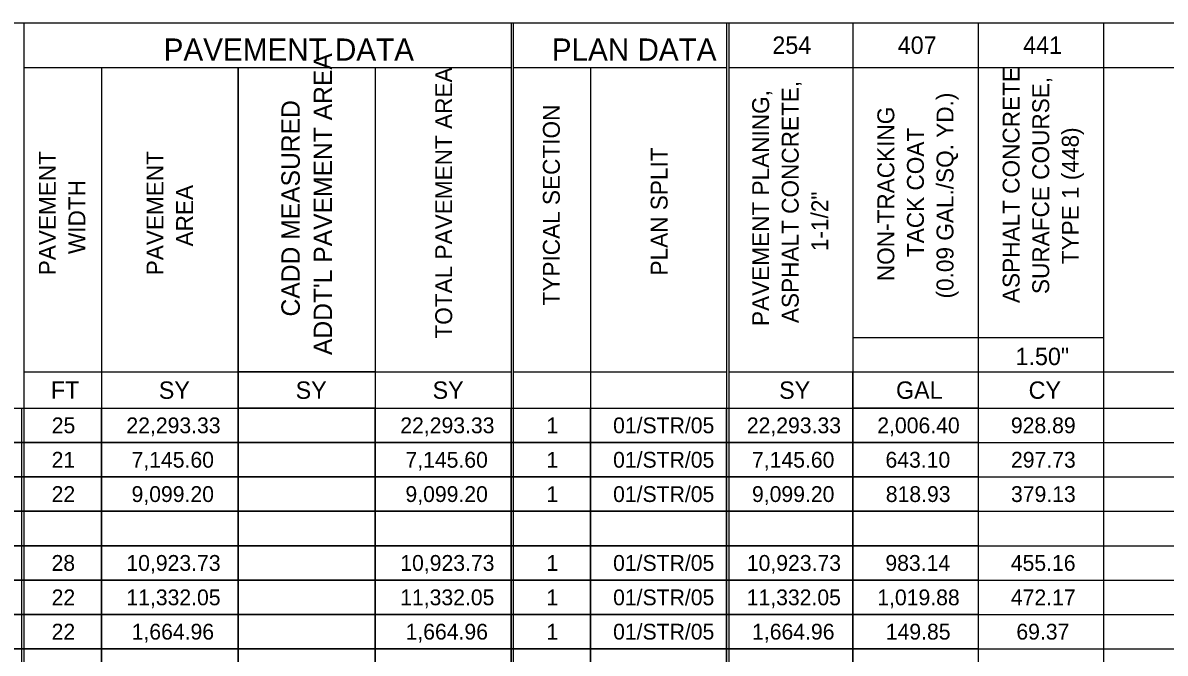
# Model space of a CAD drawing. Extents: x 0 to 34, y 0 to 22.
# Drawn here: x 9.08 to 20.36, y 6.59 to 12.82 of the extents above; entities that cross this region are included whole.
import ezdxf

# ---------------------------------------------------------------- set-up
doc = ezdxf.new("R2010")
doc.units = 0
doc.layers.add('Default', color=7, linetype='Continuous')

msp = doc.modelspace()

# ---------------------------------------------------------------- linework, layer by layer
at = {"layer": 'Default'}
for p, q in [((1.5, 12.819), (9.095, 12.819)), ((9.073, 12.819), (13.925, 12.819)), ((9.095, 12.819), (9.095, 1.862)), ((13.903, 12.819), (16.052, 12.819)), ((13.903, 12.819), (13.903, 1.183)), ((13.925, 12.819), (13.925, 1.183)), ((16.03, 12.819), (32, 12.819)), ((16.03, 12.819), (16.03, 0.503)), ((16.052, 12.819), (16.052, 0.503)), ((17.278, 12.819), (17.278, 0.503)), ((18.514, 12.819), (18.514, 0.503)), ((19.751, 12.819), (19.751, 0.503)), ((9.095, 12.378), (13.903, 12.378)), ((9.859, 12.378), (9.859, 1.862)), ((11.211, 12.378), (11.211, 1.862)), ((12.562, 12.378), (12.562, 1.862)), ((13.925, 12.378), (16.03, 12.378)), ((14.689, 12.378), (14.689, 1.862)), ((16.052, 12.378), (32, 12.378)), ((17.278, 9.711), (19.751, 9.711)), ((9.095, 9.371), (13.903, 9.371)), ((13.925, 9.371), (16.03, 9.371)), ((16.052, 9.371), (25.933, 9.371)), ((9.095, 9.014), (13.903, 9.014)), ((13.925, 9.014), (16.03, 9.014)), ((16.052, 9.014), (32, 9.014)), ((9.095, 8.674), (13.903, 8.674)), ((13.925, 8.674), (16.03, 8.674)), ((16.052, 8.674), (32, 8.674)), ((9.095, 8.335), (13.903, 8.335)), ((13.925, 8.335), (16.03, 8.335)), ((16.052, 8.335), (32, 8.335)), ((9.095, 7.995), (13.903, 7.995)), ((13.925, 7.995), (16.03, 7.995)), ((16.052, 7.995), (32, 7.995)), ((9.095, 7.655), (13.903, 7.655)), ((13.925, 7.655), (16.03, 7.655)), ((16.052, 7.655), (32, 7.655)), ((9.095, 7.315), (13.903, 7.315)), ((13.925, 7.315), (16.03, 7.315)), ((16.052, 7.315), (32, 7.315)), ((9.095, 6.976), (13.903, 6.976)), ((13.925, 6.976), (16.03, 6.976)), ((16.052, 6.976), (32, 6.976)), ((9.095, 6.636), (13.903, 6.636)), ((13.925, 6.636), (16.03, 6.636)), ((16.052, 6.636), (32, 6.636))]:
    msp.add_line(p, q, dxfattribs=at)
for points in [[(11.211, 12.378), (12.562, 12.378), (12.562, 9.371), (11.211, 9.371)], [(11.211, 9.371), (12.562, 9.371), (12.562, 9.014), (11.211, 9.014)], [(17.278, 9.371), (18.514, 9.371), (18.514, 9.014), (17.278, 9.014)], [(7.847, 9.014), (9.095, 9.014), (9.095, 8.674), (7.847, 8.674)], [(9.073, 9.014), (9.859, 9.014), (9.859, 8.674), (9.073, 8.674)], [(9.859, 9.014), (11.211, 9.014), (11.211, 8.674), (9.859, 8.674)], [(11.211, 9.014), (12.562, 9.014), (12.562, 8.674), (11.211, 8.674)], [(12.562, 9.014), (13.925, 9.014), (13.925, 8.674), (12.562, 8.674)], [(13.903, 9.014), (14.689, 9.014), (14.689, 8.674), (13.903, 8.674)], [(14.689, 9.014), (16.052, 9.014), (16.052, 8.674), (14.689, 8.674)], [(16.03, 9.014), (17.278, 9.014), (17.278, 8.674), (16.03, 8.674)], [(17.278, 9.014), (18.514, 9.014), (18.514, 8.674), (17.278, 8.674)], [(7.847, 8.674), (9.095, 8.674), (9.095, 8.335), (7.847, 8.335)], [(9.073, 8.674), (9.859, 8.674), (9.859, 8.335), (9.073, 8.335)], [(9.859, 8.674), (11.211, 8.674), (11.211, 8.335), (9.859, 8.335)], [(11.211, 8.674), (12.562, 8.674), (12.562, 8.335), (11.211, 8.335)], [(12.562, 8.674), (13.925, 8.674), (13.925, 8.335), (12.562, 8.335)], [(13.903, 8.674), (14.689, 8.674), (14.689, 8.335), (13.903, 8.335)], [(14.689, 8.674), (16.052, 8.674), (16.052, 8.335), (14.689, 8.335)], [(16.03, 8.674), (17.278, 8.674), (17.278, 8.335), (16.03, 8.335)], [(17.278, 8.674), (18.514, 8.674), (18.514, 8.335), (17.278, 8.335)], [(7.847, 8.335), (9.095, 8.335), (9.095, 7.995), (7.847, 7.995)], [(9.073, 8.335), (9.859, 8.335), (9.859, 7.995), (9.073, 7.995)], [(9.859, 8.335), (11.211, 8.335), (11.211, 7.995), (9.859, 7.995)], [(11.211, 8.335), (12.562, 8.335), (12.562, 7.995), (11.211, 7.995)], [(12.562, 8.335), (13.925, 8.335), (13.925, 7.995), (12.562, 7.995)], [(13.903, 8.335), (14.689, 8.335), (14.689, 7.995), (13.903, 7.995)], [(14.689, 8.335), (16.052, 8.335), (16.052, 7.995), (14.689, 7.995)], [(16.03, 8.335), (17.278, 8.335), (17.278, 7.995), (16.03, 7.995)], [(17.278, 8.335), (18.514, 8.335), (18.514, 7.995), (17.278, 7.995)], [(7.847, 7.995), (9.095, 7.995), (9.095, 7.655), (7.847, 7.655)], [(9.073, 7.995), (9.859, 7.995), (9.859, 7.655), (9.073, 7.655)], [(9.859, 7.995), (11.211, 7.995), (11.211, 7.655), (9.859, 7.655)], [(11.211, 7.995), (12.562, 7.995), (12.562, 7.655), (11.211, 7.655)], [(12.562, 7.995), (13.925, 7.995), (13.925, 7.655), (12.562, 7.655)], [(13.903, 7.995), (14.689, 7.995), (14.689, 7.655), (13.903, 7.655)], [(14.689, 7.995), (16.052, 7.995), (16.052, 7.655), (14.689, 7.655)], [(16.03, 7.995), (17.278, 7.995), (17.278, 7.655), (16.03, 7.655)], [(17.278, 7.995), (18.514, 7.995), (18.514, 7.655), (17.278, 7.655)], [(7.847, 7.655), (9.095, 7.655), (9.095, 7.315), (7.847, 7.315)], [(9.073, 7.655), (9.859, 7.655), (9.859, 7.315), (9.073, 7.315)], [(9.859, 7.655), (11.211, 7.655), (11.211, 7.315), (9.859, 7.315)], [(11.211, 7.655), (12.562, 7.655), (12.562, 7.315), (11.211, 7.315)], [(12.562, 7.655), (13.925, 7.655), (13.925, 7.315), (12.562, 7.315)], [(13.903, 7.655), (14.689, 7.655), (14.689, 7.315), (13.903, 7.315)], [(14.689, 7.655), (16.052, 7.655), (16.052, 7.315), (14.689, 7.315)], [(16.03, 7.655), (17.278, 7.655), (17.278, 7.315), (16.03, 7.315)], [(17.278, 7.655), (18.514, 7.655), (18.514, 7.315), (17.278, 7.315)], [(7.847, 7.315), (9.095, 7.315), (9.095, 6.976), (7.847, 6.976)], [(9.073, 7.315), (9.859, 7.315), (9.859, 6.976), (9.073, 6.976)], [(9.859, 7.315), (11.211, 7.315), (11.211, 6.976), (9.859, 6.976)], [(11.211, 7.315), (12.562, 7.315), (12.562, 6.976), (11.211, 6.976)], [(12.562, 7.315), (13.925, 7.315), (13.925, 6.976), (12.562, 6.976)], [(13.903, 7.315), (14.689, 7.315), (14.689, 6.976), (13.903, 6.976)], [(14.689, 7.315), (16.052, 7.315), (16.052, 6.976), (14.689, 6.976)], [(16.03, 7.315), (17.278, 7.315), (17.278, 6.976), (16.03, 6.976)], [(17.278, 7.315), (18.514, 7.315), (18.514, 6.976), (17.278, 6.976)], [(7.847, 6.976), (9.095, 6.976), (9.095, 6.636), (7.847, 6.636)], [(9.073, 6.976), (9.859, 6.976), (9.859, 6.636), (9.073, 6.636)], [(9.859, 6.976), (11.211, 6.976), (11.211, 6.636), (9.859, 6.636)], [(11.211, 6.976), (12.562, 6.976), (12.562, 6.636), (11.211, 6.636)], [(12.562, 6.976), (13.925, 6.976), (13.925, 6.636), (12.562, 6.636)], [(13.903, 6.976), (14.689, 6.976), (14.689, 6.636), (13.903, 6.636)], [(14.689, 6.976), (16.052, 6.976), (16.052, 6.636), (14.689, 6.636)], [(16.03, 6.976), (17.278, 6.976), (17.278, 6.636), (16.03, 6.636)], [(17.278, 6.976), (18.514, 6.976), (18.514, 6.636), (17.278, 6.636)], [(7.847, 6.636), (9.095, 6.636), (9.095, 6.296), (7.847, 6.296)], [(9.073, 6.636), (9.859, 6.636), (9.859, 6.296), (9.073, 6.296)], [(9.859, 6.636), (11.211, 6.636), (11.211, 6.296), (9.859, 6.296)], [(11.211, 6.636), (12.562, 6.636), (12.562, 6.296), (11.211, 6.296)], [(12.562, 6.636), (13.925, 6.636), (13.925, 6.296), (12.562, 6.296)], [(13.903, 6.636), (14.689, 6.636), (14.689, 6.296), (13.903, 6.296)], [(14.689, 6.636), (16.052, 6.636), (16.052, 6.296), (14.689, 6.296)], [(16.03, 6.636), (17.278, 6.636), (17.278, 6.296), (16.03, 6.296)], [(17.278, 6.636), (18.514, 6.636), (18.514, 6.296), (17.278, 6.296)]]:
    msp.add_lwpolyline(points, close=True, dxfattribs=at)

# ---------------------------------------------------------------- texts
for s, height, p in [('PAVEMENT DATA', 0.2188, (10.474, 12.446)), ('PLAN DATA', 0.2188, (14.306, 12.446)), ('254', 0.1719, (16.483, 12.513)), ('407', 0.1719, (17.721, 12.513)), ('441', 0.1719, (18.959, 12.513)), ('1.50"', 0.1719, (18.884, 9.439)), ('FT', 0.1719, (9.36, 9.106)), ('SY', 0.1719, (10.426, 9.106)), ('SY', 0.1719, (11.777, 9.106)), ('SY', 0.1719, (13.129, 9.106)), ('SY', 0.1719, (16.55, 9.106)), ('GAL', 0.1719, (17.704, 9.106)), ('CY', 0.1719, (19.013, 9.106)), ('25', 0.1563, (9.369, 8.766)), ('22,293.33', 0.1563, (10.106, 8.766)), ('22,293.33', 0.1563, (12.81, 8.766)), ('1', 0.156, (14.253, 8.766)), ('01/STR/05', 0.1563, (14.911, 8.766)), ('22,293.33', 0.1563, (16.231, 8.766)), ('2,006.40', 0.1563, (17.519, 8.766)), ('928.89', 0.1563, (18.838, 8.766)), ('21', 0.1563, (9.368, 8.426)), ('7,145.60', 0.1563, (10.157, 8.426)), ('7,145.60', 0.1563, (12.861, 8.426)), ('1', 0.156, (14.253, 8.426)), ('01/STR/05', 0.1563, (14.911, 8.426)), ('7,145.60', 0.1563, (16.282, 8.426)), ('643.10', 0.1563, (17.6, 8.426)), ('297.73', 0.1563, (18.839, 8.426)), ('22', 0.1563, (9.368, 8.087)), ('9,099.20', 0.1563, (10.157, 8.087)), ('9,099.20', 0.1563, (12.861, 8.087)), ('1', 0.156, (14.253, 8.087)), ('01/STR/05', 0.1563, (14.911, 8.087)), ('9,099.20', 0.1563, (16.282, 8.087)), ('818.93', 0.1563, (17.603, 8.087)), ('379.13', 0.1563, (18.839, 8.087)), ('28', 0.1563, (9.367, 7.407)), ('10,923.73', 0.1563, (10.106, 7.407)), ('10,923.73', 0.1563, (12.81, 7.407)), ('1', 0.156, (14.253, 7.407)), ('01/STR/05', 0.1563, (14.911, 7.407)), ('10,923.73', 0.1563, (16.231, 7.407)), ('983.14', 0.1563, (17.599, 7.407)), ('455.16', 0.1563, (18.837, 7.407)), ('22', 0.1563, (9.368, 7.067)), ('11,332.05', 0.1563, (10.106, 7.067)), ('11,332.05', 0.1563, (12.809, 7.067)), ('1', 0.156, (14.253, 7.067)), ('01/STR/05', 0.1563, (14.911, 7.067)), ('11,332.05', 0.1563, (16.23, 7.067)), ('1,019.88', 0.1563, (17.519, 7.067)), ('472.17', 0.1563, (18.838, 7.067)), ('22', 0.1563, (9.368, 6.728)), ('1,664.96', 0.1563, (10.158, 6.728)), ('1,664.96', 0.1563, (12.862, 6.728)), ('1', 0.156, (14.253, 6.728)), ('01/STR/05', 0.1563, (14.911, 6.728)), ('1,664.96', 0.1563, (16.283, 6.728)), ('149.85', 0.1563, (17.603, 6.728)), ('69.37', 0.1563, (18.892, 6.728))]:
    msp.add_text(s, height=height, dxfattribs=at).set_placement(p)
for s, height, p in [("ADDT'L PAVEMENT AREA", 0.18201, (12.137, 9.538)), ('TOTAL PAVEMENT AREA', 0.16684, (13.322, 9.701)), ('ASPHALT CONCRETE ', 0.16684, (18.924, 10.052)), ('ASPHALT CONCRETE, ', 0.16684, (16.743, 9.854)), ('SURAFCE COURSE, ', 0.16684, (19.216, 10.141)), ('PAVEMENT PLANING, ', 0.16684, (16.451, 9.825)), ('(0.09 GAL./SQ. YD.)', 0.16684, (18.271, 10.097)), ('CADD MEASURED', 0.18201, (11.818, 9.919)), ('TYPICAL SECTION', 0.16684, (14.385, 10.028)), ('NON-TRACKING ', 0.16684, (17.687, 10.268)), ('TACK COAT', 0.1668, (17.979, 10.506)), ('TYPE 1 (448)', 0.16684, (19.508, 10.435)), ('PAVEMENT', 0.1668, (9.409, 10.326)), ('PAVEMENT', 0.1668, (10.472, 10.326)), ('PLAN SPLIT', 0.1668, (15.449, 10.324)), ('WIDTH', 0.1668, (9.701, 10.536)), ('AREA', 0.1668, (10.764, 10.611)), ('1-1/2"', 0.1668, (17.035, 10.565))]:
    msp.add_text(s, height=height, rotation=90, dxfattribs=at).set_placement(p)

doc.saveas('drawing.dxf')
